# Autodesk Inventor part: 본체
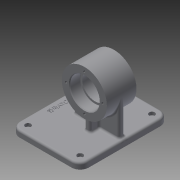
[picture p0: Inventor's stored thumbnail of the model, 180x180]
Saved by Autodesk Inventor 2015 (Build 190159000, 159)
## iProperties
Created: 2019-09
Part Number: 본체
Material: 일반
Document SubType Name: Modeling
Designer: now
Density: 1 g/cm^3
Appearance: 기본값
Author: now
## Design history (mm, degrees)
sketch "스케치1"
  geometry: L1 (-49, 63)-(49, 63); L2 (49, 63)-(49, -63); L3 (49, -63)-(-49, -63); L4 (-49, -63)-(-49, 63); L5 (-49, 63)-(49, -63); L6 (49, 63)-(-49, -63); 1 further point
  constraints: 12 end point, 2 midpoint, 2 parallel, 1 horizontal, 1 perpendicular
  dimensions: "d0" = 98 distance of L2.end L3.end; "d1" = 126 distance of L1.end L2.end
extrude "돌출1" new body sketch "스케치1" distance "d2" = 9; taper "d3" = 0 deg
fillet "모깎기1" dims "d4" = 12
sketch "스케치2"
  geometry: A1 r 12 centre (-37, 51) between (-37, 63) and (-49, 51) reference; A2 r 12 centre (-37, -51) between (-49, -51) and (-37, -63) reference; A3 r 12 centre (37, -51) between (37, -63) and (49, -51) reference; A4 r 12 centre (37, 51) between (49, 51) and (37, 63) reference; 1 further point
hole "구멍1" sketch "스케치2" at (-37, -51), (-37, 51), (37, -51), (37, 51) diameter "d5" = 4.5; stored, may be unused: countersink angle "d9" = 90 deg, drill point angle "d11" = 118 deg; dims "d6" = 6, "d7" = 8, "d8" = 4.4, "d10" = 8
sketch "스케치3"
  geometry: L1 (-49, 51)-(-49, -51) reference; L2 (45, 4)-(-19, 4); L3 (-19, 4)-(-19, -4); L4 (-19, -4)-(45, -4); L5 (45, -4)-(45, 4); L6 (45, 4)-(-19, -4); L7 (-19, 4)-(45, -4); 3 further points
  constraints: 12 end point, 3 midpoint, 2 parallel, 1 horizontal, 1 horizontal alignment, 1 perpendicular
  dimensions: "d22" = 8 distance of L2.end L3.end; "d23" = 62 distance from line of L1 point (13, 0); "d24" = 64 distance of L3.end L4.end
extrude "돌출2" join sketch "스케치3" distance "d15" = 50; taper "d16" = 0 deg
sketch "스케치4"
  geometry: L1 (-49, 51)-(-49, -51) reference; L2 (9, -17)-(17, -17); L3 (17, -17)-(17, 17); L4 (17, 17)-(9, 17); L5 (9, 17)-(9, -17); L6 (9, -17)-(17, 17); L7 (17, -17)-(9, 17); 3 further points
  constraints: 12 end point, 3 midpoint, 2 parallel, 1 horizontal, 1 horizontal alignment, 1 perpendicular
  dimensions: "d17" = 8 distance of L3.end L4.end; "d18" = 62 distance from line of L1 point (13, 0); "d19" = 34 distance of L2.end L3.end
extrude "돌출3" join sketch "스케치4" distance "d20" = 50; taper "d21" = 0 deg
sketch "스케치6"
  geometry: L1 (49, 9)-(49, 0) reference; L2 (49, 0)-(-49, 0) reference; L3 (-49, 0)-(-49, 9) reference; L4 (-49, 9)-(-45, 9) reference; L5 (-45, 9)-(-45, 59) reference; L6 (-45, 59)-(19, 59) reference; L7 (19, 59)-(19, 9) reference; L8 (19, 9)-(49, 9) reference; C1 r 32 at (-13, 59); 1 further point
  constraints: 1 centre point
  dimensions: "d25" = 64 diameter of C1; "d26" = 59 distance from line of L2 C1.centre; "d27" = 36 horizontal distance of L2.end C1.centre
extrude "돌출4" join sketch "스케치6" stored distance "d28" = 42; taper "d29" = 0 deg
sketch "스케치7"
  geometry: C1 r 32 at (0, 0) reference; C2 r 21 at (0, 0); 1 further point
  constraints: 1 centre point, 1 coincident
  dimensions: "d30" = 42 diameter of C2
extrude "돌출5" cut sketch "스케치7" distance "d31" = 15; taper "d32" = 0 deg
fillet "모깎기2" dims "d33" = 3
fillet "모깎기3" dims "d34" = 3
sketch "스케치8"
  geometry: C1 r 21 at (0, 0) reference; C2 r 18 at (0, 0); 1 further point
  constraints: 1 centre point, 1 coincident
  dimensions: "d35" = 36 diameter of C2
extrude "돌출6" cut sketch "스케치8" stored distance "d36" = 15; taper "d37" = 0 deg
sketch "스케치9"
  geometry: C1 r 32 at (0, 0) reference; C2 r 21 at (0, 0); 1 further point
  constraints: 1 centre point, 1 coincident
  dimensions: "d38" = 42 diameter of C2
extrude "돌출7" cut sketch "스케치9" distance "d39" = 15; taper "d40" = 0 deg
fillet "모깎기4" dims "d41" = 0.3
chamfer "모따기1" distance "d42" = 1; stored, may be unused: second distance "d43" = 2, angle "d44" = 45 deg
sketch "스케치10"
  geometry: C1 r 32 at (0, 0) reference; 2 further points
  constraints: 1 vertical alignment
  dimensions: "d45" = 26 distance of C1.centre point (0, 26)
hole "구멍2" sketch "스케치10" at (0, 26) diameter "d46" = 3.242; stored, may be unused: countersink angle "d50" = 90 deg, drill point angle "d52" = 118 deg; dims "d47" = 8, "d48" = 8, "d49" = 4.4, "d51" = 10
fillet "모깎기5" dims "d56" = 3
sketch "스케치11"
  geometry: L1 (-49, 51)-(-49, -51) reference; L2 (37, 63)-(-37, 63) reference; 2 further points
  constraints: 1 other
  dimensions: "d57" = 10 distance from line of L1 point (-39, 0); "d58" = 63 distance from line of point (-39, 0) L2
feature "엠보싱1" sketch "스케치11" dims "d0" = 98, "d1" = 126, "d10" = 8, "d59" = 0.5, "d60" = 0
node "솔리드1"
pattern_circular "원형 패턴1" dims angle "d54" = 360 deg
mirror "대칭1"
node "절단 모서리 투영1"
